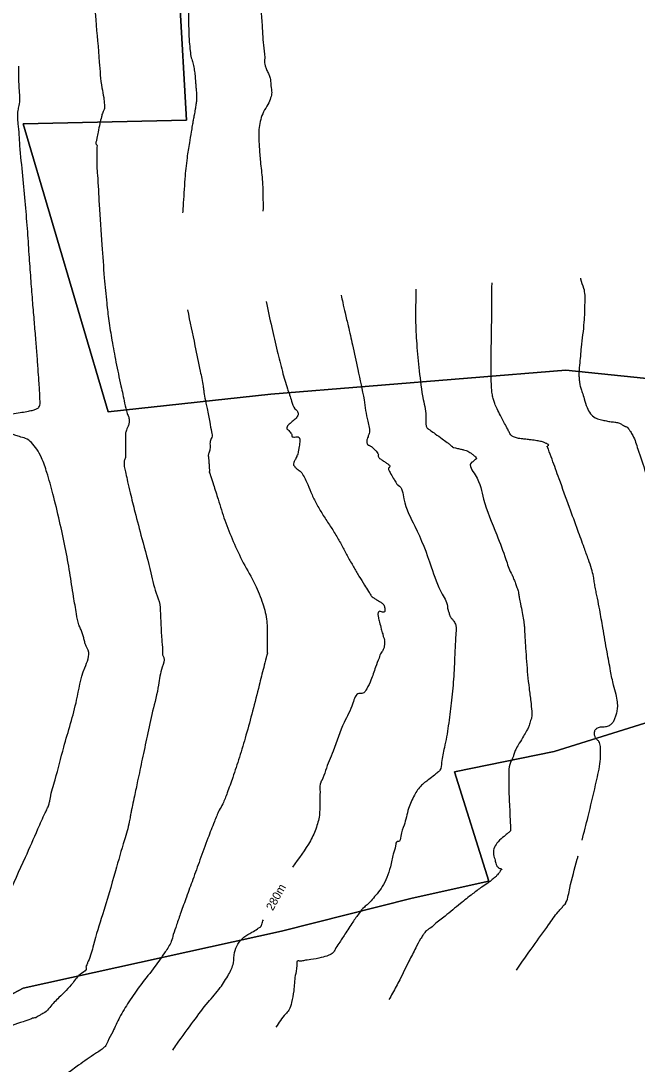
# Model space of a CAD drawing. Extents: x -478495 to -472450, y -1118050 to -1113745.
# Drawn here: x -477025.5 to -476892.7, y -1116410.3 to -1116185.5 of the extents above; entities that cross this region are included whole.
import ezdxf

# ---------------------------------------------------------------- set-up
doc = ezdxf.new("R2010")
doc.units = 0
for name, color, linetype in [('ObPÚ', 7, 'Continuous'), ('Vrstevnice_hlavni', 7, 'Continuous'), ('Vrstevnice_popis', 7, 'Continuous'), ('Vrstevnice_vedlejsi', 7, 'Continuous')]:
    doc.layers.add(name, color=color, linetype=linetype)

msp = doc.modelspace()

# ---------------------------------------------------------------- linework, layer by layer
at = {"layer": 'ObPÚ'}
for p, q in [((-476991.93, -1116169.55), (-476989.82, -1116206.87)), ((-476989.82, -1116206.87), (-476991.93, -1116169.55)), ((-476989.82, -1116206.87), (-477024.98, -1116207.7)), ((-477024.98, -1116207.7), (-476989.82, -1116206.87)), ((-477024.98, -1116207.7), (-477006.66, -1116269.72)), ((-477006.66, -1116269.72), (-477024.98, -1116207.7)), ((-476971.65, -1116265.93), (-476908.04, -1116260.74)), ((-476908.04, -1116260.74), (-476971.65, -1116265.93)), ((-476908.04, -1116260.74), (-476888.56, -1116262.76)), ((-476888.56, -1116262.76), (-476908.04, -1116260.74)), ((-477006.66, -1116269.72), (-476971.65, -1116265.93)), ((-476971.65, -1116265.93), (-477006.66, -1116269.72)), ((-476861.27, -1116327.48), (-476910.57, -1116342.96)), ((-476910.57, -1116342.96), (-476861.27, -1116327.48)), ((-476910.57, -1116342.96), (-476932.04, -1116347.33)), ((-476932.04, -1116347.33), (-476910.57, -1116342.96)), ((-476932.04, -1116347.33), (-476924.68, -1116370.92)), ((-476924.68, -1116370.92), (-476932.04, -1116347.33)), ((-476924.68, -1116370.92), (-476941.15, -1116374.54)), ((-476941.15, -1116374.54), (-476924.68, -1116370.92)), ((-476941.15, -1116374.54), (-476969.36, -1116381.65)), ((-476969.36, -1116381.65), (-476941.15, -1116374.54)), ((-476969.36, -1116381.65), (-477025, -1116393.94)), ((-477025, -1116393.94), (-476969.36, -1116381.65)), ((-477025, -1116393.94), (-477027.15, -1116395.14)), ((-477027.15, -1116395.14), (-477025, -1116393.94))]:
    msp.add_line(p, q, dxfattribs=at)
at = {"layer": 'Vrstevnice_hlavni'}
for points in [[(-476985.06, -1116145.66), (-476984.93, -1116146.19), (-476984.26, -1116148.42), (-476982.98, -1116152.63), (-476981.1, -1116158.8), (-476979.72, -1116163.12), (-476978.84, -1116165.6), (-476978.46, -1116166.23), (-476978.17, -1116166.89), (-476977.97, -1116167.59), (-476977.87, -1116168.31), (-476977.65, -1116168.92), (-476977.31, -1116169.41), (-476976.84, -1116169.77), (-476976.37, -1116170.18), (-476975.91, -1116170.63), (-476975.44, -1116171.12), (-476975.1, -1116171.53), (-476974.88, -1116171.87), (-476974.79, -1116172.13), (-476974.53, -1116174.65), (-476974.11, -1116179.43), (-476973.52, -1116186.47), (-476973.14, -1116191.34), (-476972.96, -1116194.02), (-476972.98, -1116194.52), (-476972.84, -1116195.16), (-476972.56, -1116195.94), (-476972.13, -1116196.85), (-476971.83, -1116197.59), (-476971.68, -1116198.15), (-476971.67, -1116198.55), (-476971.63, -1116199.14), (-476971.55, -1116199.93), (-476971.44, -1116200.92), (-476971.67, -1116202.11), (-476972.25, -1116203.5), (-476973.18, -1116205.09), (-476973.81, -1116206.74), (-476974.15, -1116208.45), (-476974.21, -1116210.22), (-476974.11, -1116212.68), (-476973.87, -1116215.82), (-476973.48, -1116219.66), (-476973.31, -1116224.05), (-476973.31, -1116226.48)], [(-476972.63, -1116245.95), (-476971.43, -1116251.57), (-476970.26, -1116256.66), (-476969.13, -1116261.06), (-476968.05, -1116264.77), (-476967.15, -1116267.45), (-476966.42, -1116269.09), (-476965.85, -1116269.71), (-476965.77, -1116270.37), (-476966.16, -1116271.09), (-476967.03, -1116271.86), (-476967.64, -1116272.4), (-476967.97, -1116272.7), (-476968.03, -1116272.78), (-476968.09, -1116272.88), (-476968.13, -1116273.02), (-476968.16, -1116273.2), (-476968.17, -1116273.32), (-476968.17, -1116273.39), (-476968.15, -1116273.4), (-476968.02, -1116273.53), (-476967.78, -1116273.79), (-476967.43, -1116274.16), (-476967.2, -1116274.49), (-476967.09, -1116274.78), (-476967.09, -1116275.02), (-476966.89, -1116275.16), (-476966.5, -1116275.19), (-476965.92, -1116275.12), (-476965.54, -1116275.28), (-476965.37, -1116275.66), (-476965.4, -1116276.27), (-476965.46, -1116276.91), (-476965.57, -1116277.59), (-476965.71, -1116278.31), (-476965.81, -1116278.8), (-476965.88, -1116279.07), (-476965.92, -1116279.12), (-476966.05, -1116279.38), (-476966.26, -1116279.83), (-476966.57, -1116280.48), (-476966.73, -1116280.95), (-476966.75, -1116281.24), (-476966.63, -1116281.36), (-476966.54, -1116281.46), (-476966.48, -1116281.54), (-476966.45, -1116281.61), (-476966.22, -1116281.83), (-476965.8, -1116282.19)], [(-476965.8, -1116282.19), (-476965.19, -1116282.69), (-476964.47, -1116283.76), (-476963.66, -1116285.41), (-476962.74, -1116287.62), (-476961.63, -1116289.85), (-476960.32, -1116292.1), (-476958.82, -1116294.37), (-476957.44, -1116296.61), (-476956.17, -1116298.83), (-476955.01, -1116301.02), (-476953.83, -1116303.13), (-476952.64, -1116305.16), (-476951.43, -1116307.1), (-476950.58, -1116308.47), (-476950.09, -1116309.26), (-476949.96, -1116309.48), (-476949.61, -1116309.77), (-476949.03, -1116310.15), (-476948.23, -1116310.6), (-476947.65, -1116311.01), (-476947.29, -1116311.38), (-476947.16, -1116311.71), (-476947.09, -1116312.05), (-476947.07, -1116312.4), (-476947.1, -1116312.75), (-476947.27, -1116312.93), (-476947.56, -1116312.94), (-476947.98, -1116312.77), (-476948.28, -1116312.77), (-476948.47, -1116312.95), (-476948.55, -1116313.29), (-476948.46, -1116314.01), (-476948.22, -1116315.1), (-476947.83, -1116316.56), (-476947.53, -1116317.63), (-476947.34, -1116318.31), (-476947.24, -1116318.6), (-476947.17, -1116318.79), (-476947.13, -1116318.9), (-476947.11, -1116318.91), (-476947.11, -1116319.04), (-476947.12, -1116319.3), (-476947.14, -1116319.68), (-476947.17, -1116320.03), (-476947.21, -1116320.37), (-476947.27, -1116320.68), (-476947.39, -1116321), (-476947.58, -1116321.32), (-476947.83, -1116321.66), (-476948.32, -1116322.81), (-476949.07, -1116324.78), (-476950.05, -1116327.58), (-476950.97, -1116329.46), (-476951.83, -1116330.42), (-476952.63, -1116330.46), (-476953.96, -1116332.55), (-476955.83, -1116336.69), (-476958.22, -1116342.89), (-476959.84, -1116347.05), (-476960.67, -1116349.19), (-476960.73, -1116349.3), (-476960.78, -1116349.41), (-476960.82, -1116349.5), (-476960.85, -1116349.59), (-476960.87, -1116349.66), (-476960.9, -1116349.72), (-476960.91, -1116349.76), (-476960.94, -1116349.84), (-476960.96, -1116349.94), (-476961, -1116350.07), (-476961.04, -1116351.18), (-476961.08, -1116353.26), (-476961.13, -1116356.32), (-476961.8, -1116359.3), (-476963.11, -1116362.2), (-476966.98, -1116367.86)], [(-476992.74, -1116407.3), (-476991.85, -1116406.02), (-476988.26, -1116401.07), (-476985.15, -1116397.02), (-476982.53, -1116393.86), (-476980.71, -1116391.03), (-476979.68, -1116388.51), (-476979.45, -1116386.3), (-476978.71, -1116384.47), (-476977.46, -1116383), (-476975.69, -1116381.91), (-476974.49, -1116381.17), (-476973.87, -1116380.79), (-476973.82, -1116380.76), (-476973.72, -1116380.57), (-476973.59, -1116380.22), (-476973.22, -1116379.22)]]:
    msp.add_spline(points, degree=3, dxfattribs=at)
at = {"layer": 'Vrstevnice_vedlejsi'}
for points in [[(-477022.94, -1116126.23), (-477020.81, -1116132.46), (-477018.57, -1116138.98), (-477016.22, -1116145.79), (-477013.76, -1116152.89), (-477011.79, -1116161.84), (-477010.32, -1116172.63), (-477009.34, -1116185.26), (-477008.57, -1116194.37), (-477008, -1116199.94), (-477007.63, -1116201.99), (-477007.48, -1116203.55), (-477007.54, -1116204.62), (-477007.82, -1116205.2), (-477008.12, -1116206.2), (-477008.46, -1116207.62), (-477008.84, -1116209.46), (-477009.1, -1116210.76), (-477009.27, -1116211.52), (-477009.34, -1116211.73), (-477009.34, -1116211.91), (-477009.28, -1116212.06), (-477009.14, -1116212.18), (-477009.07, -1116212.7), (-477009.07, -1116213.62), (-477009.12, -1116214.94), (-477008.97, -1116218.75), (-477008.6, -1116225.03), (-477008.03, -1116233.78), (-477007.49, -1116240.88), (-477006.98, -1116246.32), (-477006.52, -1116250.11), (-477005.85, -1116254.34), (-477004.99, -1116259.02), (-477003.92, -1116264.16), (-477003.11, -1116267.85), (-477002.55, -1116270.11), (-477002.24, -1116270.93), (-477002.14, -1116271.71), (-477002.23, -1116272.46), (-477002.53, -1116273.16), (-477002.74, -1116273.72), (-477002.87, -1116274.13), (-477002.92, -1116274.39), (-477002.94, -1116275.12), (-477002.93, -1116276.31), (-477002.91, -1116277.97), (-477002.95, -1116279.19), (-477003.04, -1116279.97), (-477003.19, -1116280.33), (-477003.25, -1116280.75), (-477003.23, -1116281.25), (-477003.13, -1116281.82), (-477002.87, -1116283.01), (-477002.47, -1116284.81), (-477001.92, -1116287.22), (-477000.9, -1116291.31), (-476999.41, -1116297.06), (-476997.45, -1116304.48), (-476996.14, -1116309.44), (-476995.48, -1116311.92), (-476995.48, -1116311.93), (-476995.42, -1116313.07), (-476995.31, -1116315.35), (-476995.13, -1116318.76), (-476994.97, -1116321.12), (-476994.82, -1116322.44), (-476994.68, -1116322.7), (-476995.01, -1116324.77), (-476995.81, -1116328.63), (-476997.08, -1116334.29), (-476998.26, -1116339.62), (-476999.33, -1116344.62), (-477000.31, -1116349.3), (-477001.01, -1116352.62), (-477001.43, -1116354.6), (-477001.57, -1116355.23), (-477001.73, -1116356.03), (-477001.91, -1116356.99), (-477002.11, -1116358.13), (-477003.18, -1116362.03), (-477005.1, -1116368.71), (-477007.89, -1116378.16), (-477009.84, -1116384.65), (-477010.94, -1116388.18), (-477011.21, -1116388.76), (-477011.37, -1116389.19), (-477011.44, -1116389.47), (-477011.4, -1116389.61), (-477012.36, -1116390.74), (-477014.31, -1116392.87), (-477017.26, -1116396), (-477019.26, -1116398.11), (-477020.33, -1116399.2), (-477020.46, -1116399.26), (-477020.74, -1116399.42), (-477021.16, -1116399.68)], [(-476989.99, -1116174.04), (-476989.91, -1116174.3), (-476989.83, -1116175.18), (-476989.76, -1116176.66), (-476989.69, -1116178.75), (-476989.61, -1116180.27), (-476989.52, -1116181.22), (-476989.42, -1116181.6), (-476989.37, -1116182.22), (-476989.36, -1116183.08), (-476989.39, -1116184.17), (-476989.37, -1116185.69), (-476989.3, -1116187.63), (-476989.19, -1116189.99), (-476989, -1116191.94), (-476988.75, -1116193.46), (-476988.42, -1116194.55), (-476988.17, -1116195.73), (-476987.98, -1116197), (-476987.88, -1116198.34), (-476987.79, -1116199.43), (-476987.71, -1116200.27), (-476987.65, -1116200.85), (-476987.62, -1116201.44), (-476987.62, -1116202.04), (-476987.65, -1116202.67), (-476987.75, -1116203.5), (-476987.91, -1116204.54), (-476988.14, -1116205.8), (-476988.33, -1116206.8), (-476988.46, -1116207.54), (-476988.55, -1116208.03), (-476988.78, -1116209.43), (-476989.16, -1116211.75), (-476989.67, -1116214.99), (-476990.14, -1116219.56), (-476990.54, -1116225.48), (-476990.63, -1116226.89)], [(-477044.51, -1116393.75), (-477043.73, -1116392.77), (-477042.28, -1116391.21), (-477041.62, -1116390.94), (-477041.01, -1116390.27), (-477040.42, -1116389.2), (-477039.88, -1116387.72), (-477038.73, -1116386.45), (-477036.97, -1116385.38), (-477034.61, -1116384.51), (-477033.02, -1116383.87), (-477032.21, -1116383.47), (-477032.18, -1116383.29), (-477030.88, -1116380.28), (-477028.31, -1116374.43), (-477024.48, -1116365.74), (-477021.79, -1116359.65), (-477020.22, -1116356.17), (-477019.79, -1116355.28), (-477019.47, -1116354.45), (-477019.24, -1116353.66), (-477019.11, -1116352.92), (-477018.1, -1116349.04), (-477016.22, -1116342.02), (-477013.45, -1116331.87), (-477011.7, -1116324.91), (-477010.98, -1116321.15), (-477011.27, -1116320.57), (-477011.54, -1116319.91), (-477011.78, -1116319.14), (-477011.99, -1116318.28), (-477012.26, -1116317.41), (-477012.59, -1116316.53), (-477012.97, -1116315.64), (-477013.48, -1116313.32), (-477014.13, -1116309.57), (-477014.92, -1116304.39), (-477015.92, -1116298.97), (-477017.13, -1116293.31), (-477018.57, -1116287.41), (-477019.86, -1116282.85), (-477021.03, -1116279.64), (-477022.06, -1116277.77), (-477023.2, -1116276.39), (-477024.44, -1116275.5), (-477025.79, -1116275.1), (-477026.78, -1116274.77), (-477027.4, -1116274.5), (-477027.67, -1116274.29), (-477027.87, -1116274.06), (-477027.99, -1116273.8), (-477028.05, -1116273.52), (-477028.64, -1116273.06), (-477029.74, -1116272.42), (-477031.37, -1116271.6), (-477031.96, -1116271), (-477031.53, -1116270.63), (-477030.07, -1116270.48), (-477028.53, -1116270.31), (-477026.92, -1116270.1), (-477025.23, -1116269.85), (-477023.86, -1116269.61), (-477022.81, -1116269.37), (-477022.08, -1116269.13), (-477021.59, -1116268.78), (-477021.35, -1116268.32), (-477021.34, -1116267.76), (-477021.35, -1116267.07), (-477021.38, -1116266.26), (-477021.43, -1116265.32), (-477021.54, -1116263.61), (-477021.71, -1116261.12), (-477021.95, -1116257.86), (-477022.23, -1116254.29), (-477022.55, -1116250.41), (-477022.9, -1116246.23), (-477023.26, -1116241.59), (-477023.63, -1116236.51), (-477024, -1116230.97), (-477024.47, -1116225.1), (-477025.03, -1116218.91), (-477025.67, -1116212.38), (-477026.02, -1116207.68), (-477026.07, -1116204.8), (-477025.82, -1116203.75), (-477025.78, -1116200.56), (-477025.94, -1116195.24)], [(-476920.02, -1116274.61), (-476920.19, -1116274.28), (-476920.6, -1116273.49), (-476921.27, -1116272.24), (-476922.17, -1116270.51), (-476922.88, -1116269.08), (-476923.38, -1116267.94), (-476923.67, -1116267.1), (-476923.9, -1116266.11), (-476924.05, -1116264.96), (-476924.12, -1116263.67), (-476924.15, -1116260.32), (-476924.12, -1116254.92), (-476924.03, -1116247.46), (-476923.97, -1116242.11), (-476923.96, -1116241.97)], [(-476904.91, -1116240.96), (-476904.89, -1116241.08), (-476904.25, -1116243.09), (-476904.01, -1116246.21), (-476904.18, -1116250.45), (-476904.76, -1116255.81), (-476905.12, -1116259.68), (-476905.25, -1116262.06), (-476905.17, -1116262.95), (-476905.07, -1116263.68), (-476904.96, -1116264.25), (-476904.83, -1116264.67), (-476904.55, -1116265.56), (-476904.1, -1116266.95), (-476903.5, -1116268.81), (-476902.73, -1116270.17), (-476901.79, -1116271.02), (-476900.68, -1116271.38), (-476899.6, -1116271.65), (-476898.56, -1116271.85), (-476897.54, -1116271.97), (-476896.76, -1116272.13), (-476896.22, -1116272.31), (-476895.92, -1116272.53), (-476895.67, -1116272.69), (-476895.49, -1116272.8), (-476895.36, -1116272.85), (-476895.21, -1116272.91), (-476895.04, -1116272.98), (-476894.85, -1116273.06), (-476894.56, -1116273.39), (-476894.16, -1116273.99), (-476893.65, -1116274.84), (-476892.56, -1116277.78), (-476890.88, -1116282.81), (-476888.63, -1116289.92), (-476887.1, -1116294.73), (-476886.3, -1116297.25), (-476886.24, -1116297.47), (-476886.15, -1116297.7), (-476886.05, -1116297.95), (-476885.92, -1116298.2), (-476885.66, -1116298.72), (-476885.25, -1116299.5), (-476884.71, -1116300.55), (-476884.31, -1116301.44), (-476884.07, -1116302.19), (-476883.97, -1116302.78), (-476883.9, -1116303.26), (-476883.85, -1116303.64), (-476883.81, -1116303.91), (-476883.75, -1116304.23), (-476883.66, -1116304.58), (-476883.55, -1116304.98), (-476883.38, -1116305.42), (-476883.17, -1116305.89), (-476882.91, -1116306.41), (-476882.44, -1116307.48), (-476881.78, -1116309.11), (-476880.92, -1116311.29), (-476880.17, -1116313.07), (-476879.53, -1116314.45)], [(-476940.36, -1116243.31), (-476940.39, -1116244.9), (-476940.45, -1116249.8), (-476940.2, -1116255.13), (-476939.65, -1116260.89), (-476938.79, -1116267.07), (-476938.22, -1116271.2), (-476937.92, -1116273.27), (-476937.9, -1116273.29), (-476937.87, -1116273.31), (-476937.82, -1116273.34), (-476937.76, -1116273.38), (-476937.23, -1116273.76), (-476936.21, -1116274.49), (-476934.72, -1116275.56), (-476933.67, -1116276.33), (-476933.07, -1116276.79), (-476932.9, -1116276.94), (-476932.77, -1116277.05), (-476932.67, -1116277.12), (-476932.61, -1116277.16), (-476932.56, -1116277.21), (-476932.51, -1116277.28), (-476932.47, -1116277.35), (-476932.17, -1116277.46), (-476931.6, -1116277.6), (-476930.77, -1116277.77), (-476930.09, -1116277.94), (-476929.55, -1116278.1), (-476929.16, -1116278.26), (-476928.72, -1116278.52), (-476928.22, -1116278.87), (-476927.68, -1116279.33), (-476927.37, -1116279.66), (-476927.29, -1116279.87), (-476927.44, -1116279.95), (-476927.59, -1116280.05), (-476927.74, -1116280.17), (-476927.89, -1116280.31), (-476928.05, -1116280.45), (-476928.22, -1116280.57), (-476928.41, -1116280.7), (-476927.6, -1116283.35), (-476925.78, -1116288.54), (-476922.96, -1116296.26), (-476920.99, -1116301.58), (-476919.87, -1116304.51), (-476919.6, -1116305.04), (-476919.32, -1116305.7), (-476919.01, -1116306.49), (-476918.67, -1116307.4), (-476918.44, -1116308.11), (-476918.3, -1116308.62), (-476918.26, -1116308.94), (-476918.1, -1116309.77), (-476917.84, -1116311.14), (-476917.46, -1116313.03), (-476917.19, -1116314.61), (-476917.03, -1116315.87), (-476916.97, -1116316.82), (-476916.88, -1116318.42), (-476916.74, -1116320.67), (-476916.55, -1116323.58), (-476916.3, -1116326.47), (-476915.99, -1116329.34), (-476915.62, -1116332.18), (-476915.43, -1116334.29), (-476915.45, -1116335.66), (-476915.65, -1116336.3), (-476915.83, -1116336.86), (-476915.99, -1116337.34), (-476916.12, -1116337.74), (-476916.52, -1116338.51), (-476917.18, -1116339.66)], [(-476956.45, -1116244.62), (-476956.13, -1116246.22), (-476955.63, -1116248.44), (-476954.95, -1116251.24), (-476954.05, -1116255.3), (-476952.91, -1116260.61), (-476951.55, -1116267.18), (-476950.73, -1116271.79), (-476950.44, -1116274.44), (-476950.69, -1116275.13), (-476950.86, -1116275.62), (-476950.94, -1116275.91), (-476950.93, -1116276), (-476950.92, -1116276.13), (-476950.91, -1116276.32), (-476950.9, -1116276.56), (-476950.83, -1116276.74), (-476950.71, -1116276.87), (-476950.53, -1116276.94), (-476950.35, -1116277.03), (-476950.15, -1116277.13), (-476949.94, -1116277.25), (-476949.66, -1116277.48), (-476949.3, -1116277.84), (-476948.86, -1116278.31), (-476948.58, -1116278.72), (-476948.46, -1116279.05), (-476948.48, -1116279.31), (-476948.39, -1116279.56), (-476948.18, -1116279.8), (-476947.85, -1116280.02), (-476947.63, -1116280.18), (-476947.52, -1116280.25), (-476947.34, -1116280.37), (-476946.97, -1116280.61), (-476946.42, -1116280.97), (-476946.08, -1116281.26), (-476945.95, -1116281.46), (-476946.02, -1116281.58), (-476946.1, -1116281.72), (-476946.2, -1116281.85), (-476946.3, -1116281.98), (-476946.15, -1116282.44), (-476945.74, -1116283.22), (-476945.08, -1116284.33), (-476944.6, -1116285.08), (-476944.31, -1116285.49), (-476944.21, -1116285.54), (-476942.97, -1116288.51), (-476940.59, -1116294.39), (-476937.06, -1116303.18), (-476934.71, -1116309.06), (-476933.54, -1116312.03), (-476933.54, -1116312.08), (-476933.52, -1116312.23), (-476933.45, -1116312.46), (-476933.35, -1116312.78), (-476933.24, -1116313.12), (-476933.12, -1116313.47), (-476932.99, -1116313.83), (-476932.85, -1116314.1), (-476932.72, -1116314.27), (-476932.6, -1116314.35), (-476932.42, -1116314.55), (-476932.21, -1116314.88), (-476931.96, -1116315.33), (-476931.79, -1116315.75), (-476931.71, -1116316.11), (-476931.71, -1116316.43), (-476931.81, -1116318.41), (-476932, -1116322.07)], [(-476989.6, -1116247.76), (-476987.96, -1116255.51), (-476986.83, -1116260.99), (-476986.2, -1116264.21), (-476986.09, -1116265.16), (-476985.81, -1116266.77), (-476985.36, -1116269.05), (-476984.74, -1116272), (-476984.4, -1116274.08), (-476984.34, -1116275.31), (-476984.56, -1116275.68), (-476984.69, -1116276.12), (-476984.74, -1116276.64), (-476984.7, -1116277.23), (-476984.73, -1116277.77), (-476984.82, -1116278.24), (-476984.98, -1116278.64), (-476985.07, -1116278.97), (-476985.1, -1116279.21), (-476985.08, -1116279.38), (-476985.03, -1116279.82), (-476984.97, -1116280.54), (-476984.88, -1116281.54), (-476984.84, -1116282.23), (-476984.85, -1116282.6), (-476984.9, -1116282.65), (-476984.92, -1116282.71), (-476984.91, -1116282.77), (-476984.85, -1116282.84), (-476984.81, -1116282.89), (-476984.79, -1116282.92), (-476984.78, -1116282.94), (-476984.74, -1116283.07), (-476984.67, -1116283.32), (-476984.55, -1116283.69), (-476983.99, -1116285.45), (-476982.98, -1116288.6), (-476981.52, -1116293.13), (-476979.71, -1116297.7), (-476977.55, -1116302.29), (-476975.05, -1116306.93), (-476973.37, -1116311.13), (-476972.5, -1116314.89), (-476972.44, -1116318.21), (-476972.4, -1116320.46), (-476972.38, -1116321.65), (-476972.37, -1116321.77), (-476972.38, -1116321.89), (-476972.41, -1116322.01), (-476972.46, -1116322.13), (-476972.52, -1116322.3), (-476972.58, -1116322.52), (-476972.64, -1116322.79), (-476973.16, -1116324.84), (-476974.13, -1116328.67), (-476975.55, -1116334.27), (-476976.98, -1116339.46), (-476978.4, -1116344.21)], [(-476904.56, -1116362.04), (-476903.28, -1116356.99), (-476901.65, -1116350.13), (-476900.75, -1116345.62), (-476900.58, -1116343.46), (-476900.64, -1116341.85), (-476900.94, -1116340.8), (-476901.47, -1116340.31), (-476901.79, -1116339.75), (-476901.9, -1116339.12), (-476901.8, -1116338.42), (-476901.37, -1116337.94), (-476900.62, -1116337.66), (-476899.55, -1116337.59), (-476898.7, -1116337.33), (-476898.08, -1116336.88), (-476897.67, -1116336.24), (-476897.34, -1116335.47), (-476897.09, -1116334.6), (-476896.91, -1116333.61), (-476896.96, -1116332.29), (-476897.25, -1116330.65), (-476897.78, -1116328.67), (-476898.43, -1116325.62), (-476899.2, -1116321.5), (-476900.1, -1116316.31), (-476900.78, -1116312.45), (-476901.25, -1116309.93), (-476901.51, -1116308.75), (-476901.74, -1116307.57), (-476901.94, -1116306.4), (-476902.12, -1116305.23), (-476902.54, -1116303.62), (-476903.21, -1116301.57), (-476904.12, -1116299.06), (-476905.48, -1116295.32), (-476907.28, -1116290.36), (-476909.53, -1116284.16), (-476911.04, -1116279.97), (-476911.83, -1116277.8), (-476911.89, -1116277.64), (-476911.95, -1116277.5), (-476912.01, -1116277.38), (-476912.08, -1116277.28), (-476912.07, -1116277.18), (-476911.97, -1116277.07), (-476911.77, -1116276.97), (-476911.84, -1116276.82), (-476912.15, -1116276.61), (-476912.71, -1116276.35), (-476913.52, -1116276.13), (-476914.58, -1116275.93), (-476915.87, -1116275.77), (-476916.92, -1116275.64), (-476917.71, -1116275.54), (-476918.26, -1116275.47), (-476918.73, -1116275.37), (-476919.15, -1116275.24), (-476919.5, -1116275.09), (-476919.79, -1116274.88), (-476920.02, -1116274.61)], [(-476932, -1116322.07), (-476932.28, -1116327.4), (-476932.75, -1116332.52), (-476933.39, -1116337.42), (-476934.23, -1116342.11), (-476934.83, -1116345.31), (-476935.2, -1116347), (-476935.35, -1116347.19), (-476936.05, -1116347.79), (-476937.32, -1116348.81), (-476939.15, -1116350.24), (-476940.69, -1116352.39), (-476941.95, -1116355.24), (-476942.91, -1116358.82), (-476943.64, -1116361.2), (-476944.13, -1116362.38), (-476944.38, -1116362.37), (-476944.76, -1116363.27), (-476945.25, -1116365.08), (-476945.87, -1116367.8), (-476946.66, -1116370.13), (-476947.61, -1116372.06), (-476948.75, -1116373.61), (-476949.77, -1116374.86), (-476950.67, -1116375.82), (-476951.47, -1116376.48), (-476952.58, -1116377.79), (-476953.98, -1116379.74), (-476955.69, -1116382.35), (-476956.95, -1116384.31), (-476957.78, -1116385.63), (-476958.17, -1116386.3), (-476959.16, -1116386.89), (-476960.77, -1116387.39), (-476962.98, -1116387.8), (-476964.55, -1116388.05), (-476965.47, -1116388.14), (-476965.75, -1116388.06), (-476966.04, -1116389.11), (-476966.36, -1116391.27), (-476966.7, -1116394.56), (-476967.16, -1116397.03), (-476967.76, -1116398.7), (-476968.47, -1116399.56), (-476970.51, -1116402.39)], [(-476917.18, -1116339.66), (-476918.1, -1116341.18), (-476918.76, -1116342.35), (-476919.15, -1116343.17), (-476919.28, -1116343.64), (-476919.49, -1116344.23), (-476919.79, -1116344.94), (-476920.17, -1116345.77), (-476920.37, -1116347.8), (-476920.37, -1116351.03), (-476920.17, -1116355.45), (-476920.05, -1116358.41), (-476919.98, -1116359.9), (-476919.98, -1116359.94), (-476919.98, -1116359.96), (-476919.98, -1116359.98), (-476919.98, -1116360), (-476919.98, -1116360.01), (-476919.98, -1116360.02), (-476919.98, -1116360.04), (-476919.99, -1116360.05), (-476920, -1116360.06), (-476920.02, -1116360.08), (-476920.47, -1116360.48), (-476921.35, -1116361.25), (-476922.67, -1116362.41), (-476923.45, -1116363.61), (-476923.69, -1116364.85), (-476923.39, -1116366.12), (-476923.15, -1116367.03), (-476922.97, -1116367.58), (-476922.86, -1116367.75), (-476922.67, -1116367.92), (-476922.42, -1116368.07), (-476922.09, -1116368.21), (-476921.91, -1116368.31), (-476921.87, -1116368.39), (-476921.97, -1116368.43), (-476922.08, -1116368.53), (-476922.19, -1116368.68), (-476922.3, -1116368.88), (-476922.51, -1116369.17), (-476922.81, -1116369.53), (-476923.21, -1116369.98), (-476923.91, -1116370.58), (-476924.91, -1116371.31), (-476926.2, -1116372.19), (-476928.17, -1116373.66), (-476930.8, -1116375.74), (-476934.1, -1116378.43), (-476936.33, -1116380.22), (-476937.47, -1116381.13), (-476937.52, -1116381.15), (-476937.65, -1116381.23), (-476937.83, -1116381.37), (-476938.09, -1116381.58), (-476938.43, -1116381.98), (-476938.86, -1116382.58), (-476939.38, -1116383.37), (-476940.39, -1116385.24), (-476941.88, -1116388.17), (-476943.86, -1116392.18), (-476945.4, -1116395.06), (-476946.18, -1116396.43)], [(-476978.4, -1116344.21), (-476979.83, -1116348.54), (-476981.02, -1116351.89), (-476981.99, -1116354.24), (-476982.72, -1116355.61), (-476983.79, -1116358.08), (-476985.17, -1116361.65), (-476986.89, -1116366.33), (-476988.43, -1116370.55), (-476989.8, -1116374.33), (-476991, -1116377.65), (-476991.94, -1116380.35), (-476992.63, -1116382.43), (-476993.07, -1116383.88), (-476994.39, -1116386.17), (-476996.58, -1116389.29), (-476999.65, -1116393.25), (-477002.2, -1116396.92), (-477004.21, -1116400.28), (-477005.69, -1116403.35), (-477006.74, -1116405.45), (-477007.34, -1116406.57), (-477007.49, -1116406.72), (-477009.39, -1116408.06), (-477013.02, -1116410.59), (-477015.51, -1116412.33)], [(-476918.73, -1116390.09), (-476915.12, -1116384.96), (-476911.78, -1116380.29), (-476909.73, -1116377.52), (-476908.95, -1116376.64), (-476908.41, -1116376.02), (-476908.1, -1116375.65), (-476908.04, -1116375.53), (-476907.21, -1116372.38), (-476905.62, -1116366.2), (-476905.43, -1116365.45)], [(-477021.16, -1116399.68), (-477021.73, -1116400.03), (-477022.14, -1116400.26), (-477022.4, -1116400.38), (-477022.51, -1116400.38), (-477023.37, -1116400.65), (-477024.99, -1116401.19), (-477027.36, -1116402), (-477029.02, -1116402.57), (-477029.96, -1116402.87), (-477030.18, -1116402.93), (-477030.2, -1116402.93)]]:
    msp.add_spline(points, degree=3, dxfattribs=at)

# ---------------------------------------------------------------- texts
at = {"layer": 'Vrstevnice_popis'}
msp.add_text(' 280m ', height=1.799, rotation=61.2301, dxfattribs=at).set_placement((-476971.52, -1116378))

doc.saveas('drawing.dxf')
